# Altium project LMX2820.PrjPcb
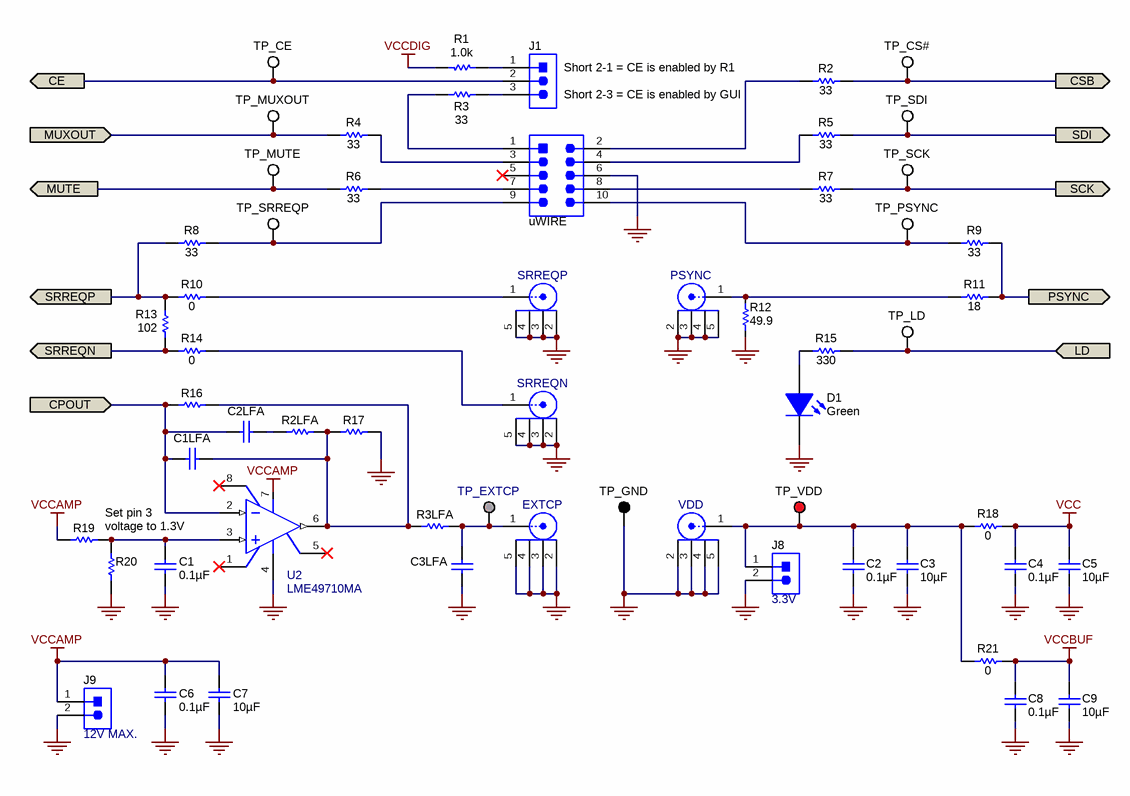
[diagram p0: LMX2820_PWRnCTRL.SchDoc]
TID: N/A; TechSupport: http://www.ti.com/support; SCH_Rev: A; PRJ_Title: LMX2820EVM; PRJ_Customer: Public Release; PCB_Rev: A; CopyrightYear: 2020
3 sheets, 127 parts. Net scope: flat (ports and power ports of the same name join across sheets).
Board file: LMX2820.PcbDoc
Sheets:
  LMX2820_PWRnCTRL.SchDoc
  LMX2820_SYNTH.SchDoc
  LMX2820_HW.SchDoc

## Sheet LMX2820_PWRnCTRL.SchDoc: Power supply and control interface
size Letter; Date: Not shown in title block; ApprovedBy: Not shown in title block; CheckedBy: Not shown in title block; Author: Not shown in title block; CompanyName: Not shown in title block; Engineer: Not shown in title block; Organization: Not shown in title block; Address1: Not shown in title block; Address2: Not shown in title block; Address3: Not shown in title block; Address4: Not shown in title block; DocumentNumber: 1; Revision: Use project parameter SCH_Rev; SheetNumber: 1; SheetTotal: 3; PageSetup: Record=PageOptions¦CenterHorizontal=True¦CenterVertical=True¦PrintScale=1.00¦XCorrection=1.00¦YCorrection=1.00¦PrintKind=0¦BorderSize=5000000¦LeftOffset=0¦BottomOffset=0¦Orientation=2¦PaperLength=1000¦PaperWidth=1000¦Scale=100¦PaperSource=15¦PrintQuality=600¦MediaType=1¦DitherType=10¦PaperKind=Letter¦PrintScaleMode=1

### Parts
C1  ValueDisplayed: 0.1µF  [0603]  (hidden comment: 885012206046)
C1LFA  885012206046  [0603]  (value not drawn)
C2  ValueDisplayed: 0.1µF  [0201_033]  (hidden comment: GRM033R61C104KE84D)
C2LFA  885012206046  [0603]  (value not drawn)
C3  ValueDisplayed: 10µF  [0603]  (hidden comment: GRM188R61A106KAALD)
C3LFA  885012206046  [0603]  (value not drawn)
C4  ValueDisplayed: 0.1µF  [0201_033]  (hidden comment: GRM033R61C104KE84D)
C5  ValueDisplayed: 10µF  [0603]  (hidden comment: GRM188R61A106KAALD)
C6  ValueDisplayed: 0.1µF  [0603]  (hidden comment: 885012206046)
C7  ValueDisplayed: 10µF  [0603]  (hidden comment: GRM188R61A106KAALD)
C8  ValueDisplayed: 0.1µF  [0201_033]  (hidden comment: GRM033R61C104KE84D)
C9  ValueDisplayed: 10µF  [0603]  (hidden comment: GRM188R61A106KAALD)
D1  value Green  [LED_LTST-C190]  (hidden comment: LTST-C190GKT)
J1  TSW-103-07-G-S  [TSW-103-07-G-S]  (value not drawn)
J2  uWIRE  [FCI_52601-S10-8LF]
J3  SRREQP  [FP-CON-SMA-EDGE-S_CONN_JACK-MFG]
J4  PSYNC  [FP-CON-SMA-EDGE-S_CONN_JACK-MFG]
J5  SRREQN  [FP-CON-SMA-EDGE-S_CONN_JACK-MFG]
J6  EXTCP  [FP-CON-SMA-EDGE-S_CONN_JACK-MFG]
J7  VDD  [FP-CON-SMA-EDGE-S_CONN_JACK-MFG]
J8  3.3V  [TSW-102-07-G-S]
J9  12V MAX.  [TSW-102-07-G-S]
R1  ValueDisplayed: 1.0k  [0603]  (hidden comment: CRCW06031K00JNEA)
R2  ValueDisplayed: 33  [0603]  (hidden comment: CRCW060333R0JNEA)
R2LFA  CRCW060333R0JNEA  [0603]  (value not drawn)
R3  ValueDisplayed: 33  [0603]  (hidden comment: CRCW060333R0JNEA)
R3LFA  CRCW06030000Z0EA  [0603]  (value not drawn)
R4  ValueDisplayed: 33  [0603]  (hidden comment: CRCW060333R0JNEA)
R5  ValueDisplayed: 33  [0603]  (hidden comment: CRCW060333R0JNEA)
R6  ValueDisplayed: 33  [0603]  (hidden comment: CRCW060333R0JNEA)
R7  ValueDisplayed: 33  [0603]  (hidden comment: CRCW060333R0JNEA)
R8  ValueDisplayed: 33  [0603]  (hidden comment: CRCW060333R0JNEA)
R9  ValueDisplayed: 33  [0603]  (hidden comment: CRCW060333R0JNEA)
R10  ValueDisplayed: 0  [0603]  (hidden comment: CRCW06030000Z0EA)
R11  ValueDisplayed: 18  [0603]  (hidden comment: CRCW060318R0JNEA)
R12  ValueDisplayed: 49.9  [0603]  (hidden comment: CRCW060349R9FKEA)
R13  ValueDisplayed: 102  [0603]  (hidden comment: CRCW0603102RFKEA)
R14  ValueDisplayed: 0  [0603]  (hidden comment: CRCW06030000Z0EA)
R15  ValueDisplayed: 330  [0603]  (hidden comment: CRCW0603330RJNEA)
R16  CRCW06030000Z0EA  [0603]  (value not drawn)
R17  CRCW06030000Z0EA  [0603]  (value not drawn)
R18  ValueDisplayed: 0  [0603]  (hidden comment: CRCW06030000Z0EA)
R19  CRCW06030000Z0EA  [0603]  (value not drawn)
R20  CRCW06030000Z0EA  [0603]  (value not drawn)
R21  ValueDisplayed: 0  [0603]  (hidden comment: CRCW06030000Z0EA)
TP1  TP_CE  [Keystone5002]
TP2  TP_CS#  [Keystone5002]
TP3  TP_MUXOUT  [Keystone5002]
TP4  TP_SDI  [Keystone5002]
TP5  TP_MUTE  [Keystone5002]
TP6  TP_SCK  [Keystone5002]
TP7  TP_SRREQP  [Keystone5002]
TP8  TP_PSYNC  [Keystone5002]
TP9  TP_LD  [Keystone5002]
TP10  TP_EXTCP  [TESTPOINT]  (no BOM)
TP11  TP_GND  [Keystone5001]
TP12  TP_VDD  [Keystone5000]
U2  LME49710MA  [D0008A_N]

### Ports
CE (out), CPOUT (in), CSB (out), LD (in), MUTE (out), MUXOUT (in), PSYNC (out), SCK (out), SDI (out), SRREQN (out), SRREQP (out)

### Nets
GND: C1.1 C2.2 C3.2 C3LFA.1 C4.2 C5.1 C6.2 C7.2 C8.2 C9.1 D1.2(K) J2.6 J3.2 J3.3 J3.4 J3.5 J4.2 J4.3 J4.4 J4.5 J5.2 J5.3 J5.4 J5.5 J6.2 J6.3 J6.4 J6.5 J7.2 J7.3 J7.4 J7.5 J8.2 J9.2 R12.1 R17.2 R20.1 TP11.1 U2.4(V-)
VCC: C4.1 C5.2 R18.1
VCCAMP: C6.1 C7.1 J9.1 R19.1 U2.7(V+)
VCCBUF: C8.1 C9.2 R21.2
VCCDIG: R1.2
CE: J1.2 TP1.1 ; port CE
CPOUT: C1LFA.1 C2LFA.1 R16.1 U2.2(-IN) ; port CPOUT
CSB: R2.2 TP2.1 ; port CSB
LD: R15.2 TP9.1 ; port LD
MUTE: R6.2 TP5.1 ; port MUTE
MUXOUT: R4.2 TP3.1 ; port MUXOUT
PSYNC: R9.2 R11.2 ; port PSYNC
SCK: R7.2 TP6.1 ; port SCK
SDI: R5.2 TP4.1 ; port SDI
SRREQN: R13.2 R14.1 ; port SRREQN
SRREQP: R8.2 R10.1 R13.1 ; port SRREQP
NetC1_2: C1.2 R19.2 R20.2 U2.3(+IN)
NetC1LFA_2: C1LFA.2 R2LFA.2 R3LFA.1 R16.2 R17.1 U2.6(OUTPUT)
NetC2_1: C2.1 C3.1 J7.1 J8.1 R18.2 R21.1 TP12.1
NetC2LFA_2: C2LFA.2 R2LFA.1
NetC3LFA_2: C3LFA.2 J6.1 R3LFA.2 TP10.1
NetD1_1: D1.1(A) R15.1
NetJ1_1: J1.1 R1.1
NetJ1_3: J1.3 R3.1
NetJ2_1: J2.1 R3.2
NetJ2_2: J2.2 R2.1
NetJ2_3: J2.3 R4.1
NetJ2_4: J2.4 R5.1
NetJ2_7: J2.7 R6.1
NetJ2_8: J2.8 R7.1
NetJ2_9: J2.9 R8.1 TP7.1
NetJ2_10: J2.10 R9.1 TP8.1
NetJ3_1: J3.1 R10.2
NetJ4_1: J4.1 R11.1 R12.2
NetJ5_1: J5.1 R14.2

Not connected (* = marked no-connect by the designer): J2 5*; U2 1(NC)* 5(NC)* 8(NC)*

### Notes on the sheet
- (near J1) Short 2-1 = CE is enabled by R1
- Short 2-3 = CE is enabled by GUI
- Set pin 3
- (near R19) voltage to 1.3V

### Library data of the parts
C1 C6 = CMP-0006829-4: CAP, CERM, 0.1 uF, 16 V, +/- 10%, X7R, 0603; Manufacturer: Wurth Elektronik; TaMin_C: -55°C; Polarized: N; SizeAreaWB_mm2: 4.68; Value1: Unknown; U/M: EA; Value: 0.1uF; TaMax_C: 125°C; SizeZ_mm: 1; SizeX_mm: 1.6; SizeY_mm: 0.8; Value2: 16V; SizeArea_mm2: 1.28; Cap_F: 100nF; AEC Category: Q200
C1LFA C2LFA C3LFA = CMP-0006829-4: CAP, CERM, 0.1 uF, 16 V, +/- 10%, X7R, 0603; Manufacturer: Wurth Elektronik; TaMin_C: -55°C; Polarized: N; SizeAreaWB_mm2: 4.68; Value1: Unknown; U/M: EA; Value: 0.1uF; TaMax_C: 125°C; SizeZ_mm: 1; SizeX_mm: 1.6; SizeY_mm: 0.8; Value2: 16V; SizeArea_mm2: 1.28; Cap_F: 100nF; AEC Category: Q200; ValueDisplayed: 0.1µF
C2 C4 C8 = CMP-0009717-2: CAP, CERM, 0.1 uF, 16 V, +/- 10%, X5R, 0201; Manufacturer: MuRata; TaMin_C: -55°C; Polarized: N; SizeAreaWB_mm2: 2.08; Value1: Unknown; U/M: EA; Value: 0.1uF; TaMax_C: 85°C; SizeZ_mm: 0.33; SizeX_mm: 0.6; SizeY_mm: 0.3; Cap_Case: 0201; Value2: 16V; SizeArea_mm2: 0.18; Cap_F: 100nF; AEC Category: Q200
C3 C5 C9 = CMP-0086193-1: CAP, CERM, 10 µF, 10 V,+/- 10%, X5R, 0603; Manufacturer: MuRata; SizeY_mm: 0.8; SizeAreaWB_mm2: 4.68; SizeX_mm: 1.6; SizeArea_mm2: 1.28; VDC_V: 10V; AEC Qualified: N; Value: 10uF; U/M: EA; SizeZ_mm: 1; TaMax_C: 85°C; AEC Category: Q200; TaMin_C: -55°C
C7 = CMP-0086193-1: CAP, CERM, 10 µF, 10 V,+/- 10%, X5R, 0603; Manufacturer: MuRata; SizeArea_mm2: 1.28; SizeY_mm: 0.8; TaMax_C: 85°C; TaMin_C: -55°C; VDC_V: 10V; Polarized: N; SizeAreaWB_mm2: 4.68; SizeZ_mm: 1; SizeX_mm: 1.6; AEC Category: Q200; U/M: EA; Value: 10uF
D1 = CMP-0002827-3: LED, Green, SMD; Manufacturer: Lite-On; Power_TotalModule: 100mW; Value2: 2.1V; Io_A: 20mA; Value1: 0.1W
J1 = CMP-0075407-2: Header, 100mil, 3x1, Gold, TH; Manufacturer: Samtec; Pitch_mm: 2.54; Cert_VDE: N; Gender: Male; Cert_CSA: Y; Voltage_V: 550V; Green_REACh: Passed; Current_A: 6.3A; Green_Lifecycle: Active; Row_Count: 1
J2 = CMP-0055434-2: Header (shrouded), 100mil, 5x2, Gold, SMT; Manufacturer: FCI; PartNumber: 52601-S10-8LF; Green_Lifecycle: Active; Green_REACh: Passed
J3-J7 = CMP-0088000-4: CONN SMA JACK STR EDGE MNT; Manufacturer: RF Solutions Ltd.; PartNumber: CON-SMA-EDGE-S; ContactFinish: Gold; Shrouded: true
J8 = CMP-0075405-3: Header, 100mil, 2x1, Gold, TH; Manufacturer: Samtec; Current_A: 6.3A; Green_Lifecycle: Active; Pitch_mm: 2.54; Cert_CSA: Y; Cert_VDE: N; Green_REACh: Passed; Row_Count: 1; Gender: Male; Voltage_V: 550V
J9 = CMP-0075405-3: Header, 100mil, 2x1, Gold, TH; Manufacturer: Samtec; Pitch_mm: 2.54; Cert_VDE: N; Gender: Male; Cert_CSA: Y; Voltage_V: 550V; Green_REACh: Passed; Current_A: 6.3A; Green_Lifecycle: Active; Row_Count: 1
R1 = CMP-0025729-4: RES, 1.0 k, 5%, 0.1 W, AEC-Q200 Grade 0, 0603; Manufacturer: Vishay-Dale; SizeY_mm: 0.8; AEC Grade: 0; TempCo: 200 ppm/C; SizeX_mm: 1.6; SizeArea_mm2: 1.28; VDC_V: 75V; AEC Qualified: Y; Value: 1.0k; SizeZ_mm: 1; AEC Category: Q200; Value2: 0.1W; Power_W: 100mW; Value_Code: 1k00; EIA_Code: E24; Res_ohm: 1k
R2 R2LFA R4-R7 R9 = CMP-0025787-4: RES, 33, 5%, 0.1 W, AEC-Q200 Grade 0, 0603; Manufacturer: Vishay-Dale; Power_W: 100mW; TempCo: 200 ppm/C; Value_Code: 33R0; Value: 33; EIA_Code: E24; SizeX_mm: 1.6; SizeY_mm: 0.8; SizeZ_mm: 1; Value2: 0.1W; SizeArea_mm2: 1.28; AEC Qualified: Y; VDC_V: 75V; AEC Category: Q200; AEC Grade: 0
R3 = CMP-0025787-4: RES, 33, 5%, 0.1 W, AEC-Q200 Grade 0, 0603; Manufacturer: Vishay-Dale; TempCo: 200 ppm/C; Value: 33; SizeZ_mm: 1; SizeX_mm: 1.6; SizeY_mm: 0.8; Value2: 0.1W; SizeArea_mm2: 1.28; AEC Qualified: Y; VDC_V: 75V; AEC Grade: 0; AEC Category: Q200; Power_W: 100mW; Value_Code: 33R0; EIA_Code: E24
R3LFA R16 R17 R19 R20 = CMP-0025697-4: RES, 0, 5%, 0.1 W, AEC-Q200 Grade 0, 0603; Manufacturer: Vishay-Dale; Power_W: 100mW; TempCo: 200 ppm/C; Value_Code: 0000; Value: 0; EIA_Code: E24; SizeX_mm: 1.6; SizeY_mm: 0.8; SizeZ_mm: 1; Value2: 0.1W; SizeArea_mm2: 1.28; AEC Qualified: Y; VDC_V: 75V; AEC Category: Q200
R8 = CMP-0025787-4: RES, 33, 5%, 0.1 W, AEC-Q200 Grade 0, 0603; Manufacturer: Vishay-Dale; Power_W: 100mW; TempCo: 200 ppm/C; Value_Code: 33R0; Value: 33; EIA_Code: E24; SizeX_mm: 1.6; SizeY_mm: 0.8; SizeZ_mm: 1; Value2: 0.1W; SizeArea_mm2: 1.28; AEC Qualified: Y; AEC Grade: 0; AEC Category: Q200; VDC_V: 75V
R10 R14 R21 = CMP-0025697-4: RES, 0, 5%, 0.1 W, AEC-Q200 Grade 0, 0603; Manufacturer: Vishay-Dale; Power_W: 100mW; TempCo: 200 ppm/C; Value_Code: 0000; Value: 0; EIA_Code: E24; SizeX_mm: 1.6; SizeY_mm: 0.8; SizeZ_mm: 1; Value2: 0.1W; SizeArea_mm2: 1.28; AEC Qualified: Y; AEC Category: Q200; VDC_V: 75V
R11 = CMP-0025728-4: RES, 18, 5%, 0.1 W, AEC-Q200 Grade 0, 0603; Manufacturer: Vishay-Dale; Power_W: 100mW; TempCo: 200 ppm/C; Value_Code: 18R0; Value: 18; EIA_Code: E24; SizeX_mm: 1.6; SizeY_mm: 0.8; SizeZ_mm: 1; Value2: 0.1W; SizeArea_mm2: 1.28; AEC Qualified: Y; VDC_V: 75V; AEC Category: Q200; AEC Grade: 0
R12 = CMP-0022448-4: RES, 49.9, 1%, 0.1 W, AEC-Q200 Grade 0, 0603; Manufacturer: Vishay-Dale; Power_W: 100mW; TempCo: 100 ppm/C; Value_Code: 49R9; Value: 49.9; EIA_Code: E96; SizeX_mm: 1.6; SizeY_mm: 0.8; SizeZ_mm: 1; Value2: 0.1W; SizeArea_mm2: 1.28; AEC Qualified: Y; VDC_V: 75V; AEC Category: Q200; AEC Grade: 0
R13 = CMP-0021993-5: RES, 102, 1%, 0.1 W, AEC-Q200 Grade 0, 0603; Manufacturer: Vishay-Dale; Power_W: 100mW; TempCo: 100 ppm/C; Value_Code: 102R; Value: 102; EIA_Code: E96; SizeX_mm: 1.6; SizeY_mm: 0.8; SizeZ_mm: 1; Value2: 0.1W; SizeArea_mm2: 1.28; AEC Qualified: Y; VDC_V: 75V; AEC Category: Q200; AEC Grade: 0
R15 = CMP-0025785-4: RES, 330, 5%, 0.1 W, AEC-Q200 Grade 0, 0603; Manufacturer: Vishay-Dale; Power_W: 100mW; TempCo: 200 ppm/C; Value_Code: 330R; Value: 330; EIA_Code: E24; SizeX_mm: 1.6; SizeY_mm: 0.8; SizeZ_mm: 1; Value2: 0.1W; SizeArea_mm2: 1.28; AEC Qualified: Y; VDC_V: 75V; AEC Category: Q200; AEC Grade: 0
R18 = CMP-0025697-4: RES, 0, 5%, 0.1 W, AEC-Q200 Grade 0, 0603; Manufacturer: Vishay-Dale; Value: 0; SizeZ_mm: 1; SizeX_mm: 1.6; SizeY_mm: 0.8; Value2: 0.1W; SizeArea_mm2: 1.28; Power_W: 100mW; TempCo: 200 ppm/C; Value_Code: 0000; EIA_Code: E24; AEC Qualified: Y; VDC_V: 75V; AEC Category: Q200
TP1 TP3 TP7 TP9 = CMP-0055139-1: Test Point, Miniature, White, TH; Manufacturer: Keystone; CNHeader: FALSE; Green_Lifecycle: Active; Green_REACh: Passed; ContactFinish: Silver; CT: TRUE
TP2 TP4-TP6 TP8 = CMP-0055139-1: Test Point, Miniature, White, TH; Manufacturer: Keystone; ContactFinish: Silver; Green_Lifecycle: Active; Green_REACh: Passed; CNHeader: FALSE; CT: TRUE
TP10 = CMP-0078143-3: TEST POINT.  No entry in BOM.
TP11 = CMP-0055138-1: Test Point, Miniature, Black, TH; Manufacturer: Keystone; ContactFinish: Silver; Green_Lifecycle: Active; Green_REACh: Passed; CNHeader: FALSE; CT: TRUE
TP12 = CMP-0055137-1: Test Point, Miniature, Red, TH; Manufacturer: Keystone; ContactFinish: Silver; Green_Lifecycle: Active; Green_REACh: Passed; CNHeader: FALSE; CT: TRUE
U2 = CMP-0068996-2: High Performance, High Fidelity Audio Operational Amplifier, 8-pin Narrow SOIC, Pb-Free; Manufacturer: Texas Instruments; PartNumber: LME49710MA/NOPB; CompType: IC; AEC Category: Q200; AEC Qualified: N; SizeAreaWB_mm2: 56.58; SizeArea_mm2: 30.38; SizeX_mm: 4.9; SizeY_mm: 6.2; SizeZ_mm: 1.75

## Sheet LMX2820_SYNTH.SchDoc: Synthesizer
size Letter; Date: Not shown in title block; ApprovedBy: Not shown in title block; CheckedBy: Not shown in title block; Author: Not shown in title block; CompanyName: Not shown in title block; Engineer: Not shown in title block; Organization: Not shown in title block; Address1: Not shown in title block; Address2: Not shown in title block; Address3: Not shown in title block; Address4: Not shown in title block; DocumentNumber: 2; Revision: Use project parameter SCH_Rev; SheetNumber: 2; SheetTotal: 3; PageSetup: Record=PageOptions¦CenterHorizontal=True¦CenterVertical=True¦PrintScale=1.00¦XCorrection=1.00¦YCorrection=1.00¦PrintKind=0¦BorderSize=5000000¦LeftOffset=0¦BottomOffset=0¦Orientation=2¦PaperLength=1000¦PaperWidth=1000¦Scale=100¦PaperSource=15¦PrintQuality=600¦MediaType=1¦DitherType=10¦PaperKind=Letter¦PrintScaleMode=1
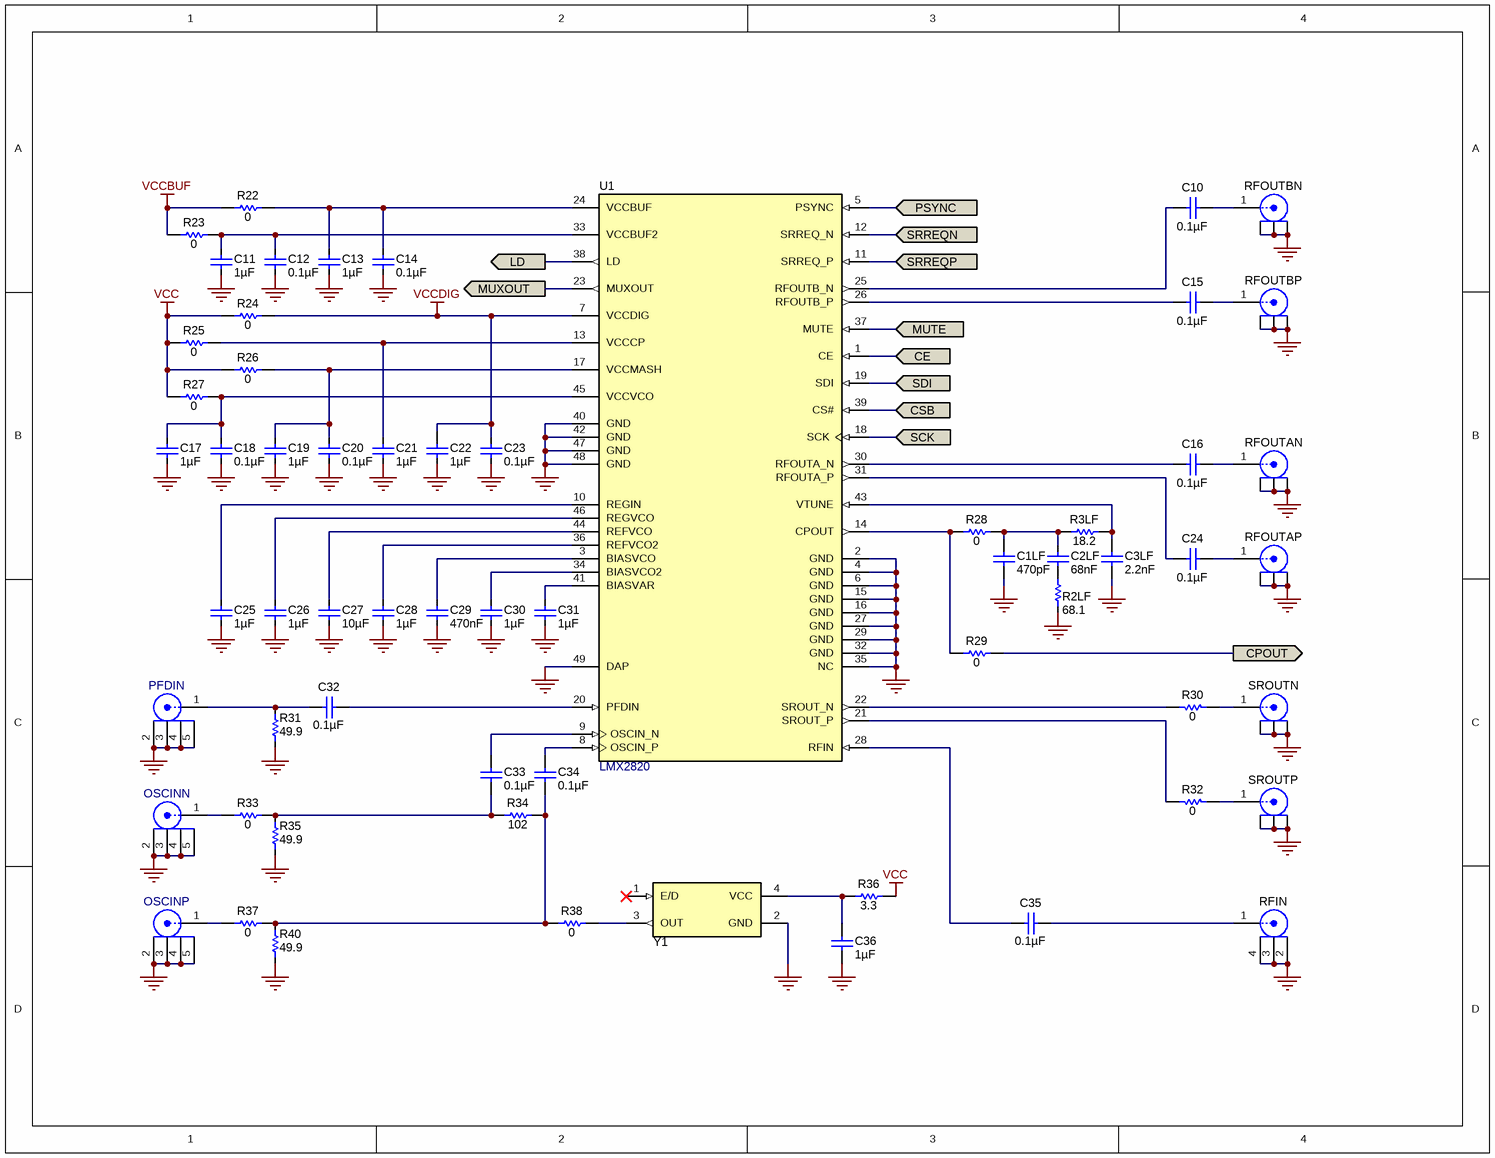
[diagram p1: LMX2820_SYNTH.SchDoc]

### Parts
C1LF  ValueDisplayed: 470pF  [0603]  (hidden comment: 885012006012)
C2LF  Cap_F: 68nF  [0603]  (hidden comment: 885012206070)
C3LF  Cap_F: 2.2nF  [0603]  (hidden comment: 885012206036)
C10  ValueDisplayed: 0.1µF  [0201_033L]  (hidden comment: ATC530Z104KT10T)
C11  ValueDisplayed: 1µF  [0402]  (hidden comment: GRM155R61E105KA12D)
C12  ValueDisplayed: 0.1µF  [0201_033]  (hidden comment: GRM033R61C104KE84D)
C13  ValueDisplayed: 1µF  [0402]  (hidden comment: GRM155R61E105KA12D)
C14  ValueDisplayed: 0.1µF  [0201_033]  (hidden comment: GRM033R61C104KE84D)
C15  ValueDisplayed: 0.1µF  [0201_033L]  (hidden comment: ATC530Z104KT10T)
C16  ValueDisplayed: 0.1µF  [0201_033L]  (hidden comment: ATC530Z104KT10T)
C17  ValueDisplayed: 1µF  [0402]  (hidden comment: GRM155R61E105KA12D)
C18  ValueDisplayed: 0.1µF  [0201_033]  (hidden comment: GRM033R61C104KE84D)
C19  ValueDisplayed: 1µF  [0402]  (hidden comment: GRM155R61E105KA12D)
C20  ValueDisplayed: 0.1µF  [0201_033]  (hidden comment: GRM033R61C104KE84D)
C21  ValueDisplayed: 1µF  [0402]  (hidden comment: GRM155R61E105KA12D)
C22  ValueDisplayed: 1µF  [0402]  (hidden comment: GRM155R61E105KA12D)
C23  ValueDisplayed: 0.1µF  [0201_033]  (hidden comment: GRM033R61C104KE84D)
C24  ValueDisplayed: 0.1µF  [0201_033L]  (hidden comment: ATC530Z104KT10T)
C25  ValueDisplayed: 1µF  [0402]  (hidden comment: GRM155R61E105KA12D)
C26  ValueDisplayed: 1µF  [0402]  (hidden comment: GRM155R61E105KA12D)
C27  ValueDisplayed: 10µF  [0603]  (hidden comment: GRM188R61A106KAALD)
C28  ValueDisplayed: 1µF  [0402]  (hidden comment: GRM155R61E105KA12D)
C29  Cap_F: 470nF  [0603]  (hidden comment: CGA3E3X7R1E474K080AB)
C30  ValueDisplayed: 1µF  [0402]  (hidden comment: GRM155R61E105KA12D)
C31  ValueDisplayed: 1µF  [0402]  (hidden comment: GRM155R61E105KA12D)
C32  ValueDisplayed: 0.1µF  [0201_033]  (hidden comment: GRM033R61C104KE84D)
C33  ValueDisplayed: 0.1µF  [0201_033]  (hidden comment: GRM033R61C104KE84D)
C34  ValueDisplayed: 0.1µF  [0201_033]  (hidden comment: GRM033R61C104KE84D)
C35  ValueDisplayed: 0.1µF  [0201_033L]  (hidden comment: ATC530Z104KT10T)
C36  Cap_F: 1µF  [0603]  (hidden comment: 885012206052)
J10  RFOUTBN  [Johnson_142-0771-831]
J11  RFOUTBP  [Johnson_142-0771-831]
J12  RFOUTAN  [Johnson_142-0771-831]
J13  RFOUTAP  [Johnson_142-0771-831]
J14  PFDIN  [FP-CON-SMA-EDGE-S_CONN_JACK-MFG]
J15  SROUTN  [Johnson_142-0771-831]
J16  SROUTP  [Johnson_142-0771-831]
J17  OSCINN  [FP-CON-SMA-EDGE-S_CONN_JACK-MFG]
J18  OSCINP  [FP-CON-SMA-EDGE-S_CONN_JACK-MFG]
J19  RFIN  [Johnson_142-0771-831]
R2LF  ValueDisplayed: 68.1  [0603]  (hidden comment: CRCW060368R1FKEA)
R3LF  ValueDisplayed: 18.2  [0603]  (hidden comment: CRCW060318R2FKEA)
R22  ValueDisplayed: 0  [0603]  (hidden comment: CRCW06030000Z0EA)
R23  ValueDisplayed: 0  [0603]  (hidden comment: CRCW06030000Z0EA)
R24  ValueDisplayed: 0  [0603]  (hidden comment: CRCW06030000Z0EA)
R25  ValueDisplayed: 0  [0603]  (hidden comment: CRCW06030000Z0EA)
R26  ValueDisplayed: 0  [0603]  (hidden comment: CRCW06030000Z0EA)
R27  ValueDisplayed: 0  [0603]  (hidden comment: CRCW06030000Z0EA)
R28  ValueDisplayed: 0  [0603]  (hidden comment: CRCW06030000Z0EA)
R29  ValueDisplayed: 0  [0603]  (hidden comment: CRCW06030000Z0EA)
R30  ValueDisplayed: 0  [0201]  (hidden comment: CRCW02010000Z0ED)
R31  ValueDisplayed: 49.9  [0603]  (hidden comment: CRCW060349R9FKEA)
R32  ValueDisplayed: 0  [0201]  (hidden comment: CRCW02010000Z0ED)
R33  ValueDisplayed: 0  [0603]  (hidden comment: CRCW06030000Z0EA)
R34  ValueDisplayed: 102  [0603]  (hidden comment: CRCW0603102RFKEA)
R35  ValueDisplayed: 49.9  [0603]  (hidden comment: CRCW060349R9FKEA)
R36  ValueDisplayed: 3.3  [0603]  (hidden comment: CRCW06033R30JNEA)
R37  ValueDisplayed: 0  [0603]  (hidden comment: CRCW06030000Z0EA)
R38  ValueDisplayed: 0  [0603]  (hidden comment: CRCW06030000Z0EA)
R40  ValueDisplayed: 49.9  [0603]  (hidden comment: CRCW060349R9FKEA)
U1  LMX2820  [RTC0048A]
Y1  CWX813-100.0M  [OSC_CWX]  (value not drawn)

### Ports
CE (in), CPOUT (out), CSB (in), LD (out), MUTE (in), MUXOUT (out), PSYNC (in), SCK (in), SDI (in), SRREQN (in), SRREQP (in)

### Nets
GND: C1LF.2 C3LF.2 C11.2 C12.2 C13.1 C14.1 C17.2 C18.2 C19.2 C20.1 C21.2 C22.2 C23.1 C25.2 C26.2 C27.1 C28.1 C29.2 C30.1 C31.2 C36.2 J10.2 J10.3 J10.4 J11.2 J11.3 J11.4 J12.2 J12.3 J12.4 J13.2 J13.3 J13.4 J14.2 J14.3 J14.4 J14.5 J15.2 J15.3 J15.4 J16.2 J16.3 J16.4 J17.2 J17.3 J17.4 J17.5 J18.2 J18.3 J18.4 J18.5 J19.2 J19.3 J19.4 R2LF.1 R31.1 R35.1 R40.2 U1.2(GND) U1.4(GND) U1.6(GND) U1.15(GND) U1.16(GND) U1.27(GND) U1.29(GND) U1.32(GND) U1.35(NC) U1.40(GND) U1.42(GND) U1.47(GND) U1.48(GND) U1.49(DAP) Y1.2(GND)
VCC: R24.2 R25.2 R26.2 R27.2 R36.2
VCCBUF: R22.2 R23.2
VCCDIG: C22.1 C23.2 R24.1 U1.7(VCCDIG)
CE: U1.1(CE) ; port CE
CPOUT: R29.1 ; port CPOUT
CSB: U1.39(CS#) ; port CSB
LD: U1.38(LD) ; port LD
MUTE: U1.37(MUTE) ; port MUTE
MUXOUT: U1.23(MUXOUT) ; port MUXOUT
PSYNC: U1.5(PSYNC) ; port PSYNC
SCK: U1.18(SCK) ; port SCK
SDI: U1.19(SDI) ; port SDI
SRREQN: U1.12(SRREQ_N) ; port SRREQN
SRREQP: U1.11(SRREQ_P) ; port SRREQP
NetC1LF_1: C1LF.1 C2LF.1 R3LF.2 R28.1
NetC2LF_2: C2LF.2 R2LF.2
NetC3LF_1: C3LF.1 R3LF.1 U1.43(VTUNE)
NetC10_1: C10.1 J10.1
NetC10_2: C10.2 U1.25(RFOUTB_N)
NetC11_1: C11.1 C12.1 R23.1 U1.33(VCCBUF2)
NetC13_2: C13.2 C14.2 R22.1 U1.24(VCCBUF)
NetC15_1: C15.1 J11.1
NetC15_2: C15.2 U1.26(RFOUTB_P)
NetC16_1: C16.1 J12.1
NetC16_2: C16.2 U1.30(RFOUTA_N)
NetC17_1: C17.1 C18.1 R27.1 U1.45(VCCVCO)
NetC19_1: C19.1 C20.2 R26.1 U1.17(VCCMASH)
NetC21_1: C21.1 R25.1 U1.13(VCCCP)
NetC24_1: C24.1 J13.1
NetC24_2: C24.2 U1.31(RFOUTA_P)
NetC25_1: C25.1 U1.10(REGIN)
NetC26_1: C26.1 U1.46(REGVCO)
NetC27_2: C27.2 U1.44(REFVCO)
NetC28_2: C28.2 U1.36(REFVCO2)
NetC29_1: C29.1 U1.3(BIASVCO)
NetC30_2: C30.2 U1.34(BIASVCO2)
NetC31_1: C31.1 U1.41(BIASVAR)
NetC32_1: C32.1 U1.20(PFDIN)
NetC32_2: C32.2 J14.1 R31.2
NetC33_1: C33.1 U1.9(OSCIN_N)
NetC33_2: C33.2 R33.2 R34.1 R35.2
NetC34_1: C34.1 U1.8(OSCIN_P)
NetC34_2: C34.2 R34.2 R37.2 R38.2 R40.1
NetC35_1: C35.1 U1.28(RFIN)
NetC35_2: C35.2 J19.1
NetC36_1: C36.1 R36.1 Y1.4(VCC)
NetJ15_1: J15.1 R30.2
NetJ16_1: J16.1 R32.2
NetJ17_1: J17.1 R33.1
NetJ18_1: J18.1 R37.1
NetR28_2: R28.2 R29.2 U1.14(CPOUT)
NetR30_1: R30.1 U1.22(SROUT_N)
NetR32_1: R32.1 U1.21(SROUT_P)
NetR38_1: R38.1 Y1.3(OUT)

Not connected (* = marked no-connect by the designer): Y1 1(E/D)*

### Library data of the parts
C1LF = CMP-0080734-1: CAP, CERM, 470 pF, 10 V,+/- 5%, C0G/NP0, 0603; Manufacturer: Wurth Elektronik; TaMin_C: -55°C; Polarized: N; SizeAreaWB_mm2: 4.68; U/M: EA; Value: 470pF; TaMax_C: 125°C; SizeZ_mm: 1; SizeX_mm: 1.6; SizeY_mm: 0.8; Value2: 10V; SizeArea_mm2: 1.28; AEC Category: Q200
C2LF = CMP-0750069-1: CAP, CERM, 0.068 µF, 25 V,+/- 10%, X7R, 0603; Manufacturer: Wurth Elektronik; TaMin_C: -55°C; Polarized: N; SizeAreaWB_mm2: 4.68; U/M: EA; Value: 0.068uF; TaMax_C: 125°C; SizeZ_mm: 1; SizeX_mm: 1.6; SizeY_mm: 0.8; Value2: 25V; SizeArea_mm2: 1.28; AEC Category: Q200
C3LF = CMP-0006827-4: CAP, CERM, 2200 pF, 16 V, +/- 10%, X7R, 0603; Manufacturer: Wurth Elektronik; AEC Qualified: N; TaMin_C: -55°C; AEC Category: Q200; SizeZ_mm: 1; SizeY_mm: 0.8; ValueDisplayed: 2200pF; SizeArea_mm2: 1.28; Value2: 16V; U/M: EA; SizeX_mm: 1.6; SizeAreaWB_mm2: 4.68; Value1: Unknown; TaMax_C: 125°C; Value: 2200pF
C10 C15 C16 C24 C35 = CMP-0076713-1: CAP, CERM, 0.1 µF, 10 V,+/- 10%, X5R, 0201; Manufacturer: American Technical Ceramics; TaMin_C: -55°C; Polarized: N; SizeAreaWB_mm2: 2.08; U/M: EA; Value: 0.1uF; TaMax_C: 85°C; SizeZ_mm: 0.33; SizeX_mm: 0.6; SizeY_mm: 0.3; Cap_Case: 0201; Value2: 10V; SizeArea_mm2: 0.18; AEC Qualified: No; Cap_F: 100nF; AEC Category: Q200
C11 C13 C17 C19 C21 C22 C25 C26 C30 = CMP-0006608-2: CAP, CERM, 1 uF, 25 V, +/- 10%, X5R, 0402; Manufacturer: MuRata; TaMin_C: -55°C; Polarized: N; SizeAreaWB_mm2: 3; Value1: Unknown; U/M: EA; Value: 1uF; TaMax_C: 85°C; SizeZ_mm: 0.6; SizeX_mm: 1; SizeY_mm: 0.5; Value2: 25V; AEC Category: Q200
C12 C14 C18 C20 C23 = CMP-0009717-2: CAP, CERM, 0.1 uF, 16 V, +/- 10%, X5R, 0201; Manufacturer: MuRata; U/M: EA; TaMax_C: 85°C; Value2: 16V; SizeZ_mm: 0.33; AEC Qualified: N; TaMin_C: -55°C; SizeY_mm: 0.3; AEC Category: Q200; Cap_Case: 0201; Value1: Unknown; SizeAreaWB_mm2: 2.08; Cap_F: 100nF; SizeX_mm: 0.6; Value: 0.1uF; SizeArea_mm2: 0.18
C27 = CMP-0086193-1: as C3 on sheet LMX2820_PWRnCTRL
C28 C31 = CMP-0006608-2: CAP, CERM, 1 uF, 25 V, +/- 10%, X5R, 0402; Manufacturer: MuRata; SizeY_mm: 0.5; SizeAreaWB_mm2: 3; SizeX_mm: 1; VDC_V: 25V; Value1: Unknown; Value: 1uF; U/M: EA; SizeZ_mm: 0.6; TaMax_C: 85°C; AEC Category: Q200; Polarized: N; TaMin_C: -55°C
C29 = CMP-0007092-5: CAP, CERM, 0.47 uF, 25 V, +/- 10%, X7R, AEC-Q200 Grade 1, 0603; Manufacturer: TDK; TaMin_C: -55°C; Polarized: N; SizeAreaWB_mm2: 4.68; Value1: Unknown; U/M: EA; Value: 0.47uF; TaMax_C: 125°C; SizeZ_mm: 1; SizeX_mm: 1.6; SizeY_mm: 0.8; Value2: 25V; SizeArea_mm2: 1.28; AEC Qualified: Y; AEC Category: Q200
C32-C34 = CMP-0009717-2: as C2 on sheet LMX2820_PWRnCTRL
C36 = CMP-0006831-4: CAP, CERM, 1 uF, 16 V, +/- 10%, X7R, 0603; Manufacturer: Wurth Elektronik; TaMin_C: -55°C; Polarized: N; SizeAreaWB_mm2: 4.68; Value1: Unknown; U/M: EA; Value: 1uF; TaMax_C: 125°C; SizeZ_mm: 1; SizeX_mm: 1.6; SizeY_mm: 0.8; Value2: 16V; SizeArea_mm2: 1.28; AEC Category: Q200
J10-J13 J15 J16 J19 = CMP-0055844-3: JACK, SMA, 50 Ohm, Gold, Edge Mount; PartNumber: 142-0771-831; Manufacturer: Cinch Connectivity; Voltage_V: 170V; Gender: Female
J14 J17 J18 = CMP-0088000-4: as J3 on sheet LMX2820_PWRnCTRL
R2LF = CMP-0022553-4: RES, 68.1, 1%, 0.1 W, AEC-Q200 Grade 0, 0603; Manufacturer: Vishay-Dale; Power_W: 100mW; TempCo: 100 ppm/C; Value_Code: 68R1; Value: 68.1; EIA_Code: E96; SizeX_mm: 1.6; SizeY_mm: 0.8; SizeZ_mm: 1; Value2: 0.1W; SizeArea_mm2: 1.28; AEC Qualified: Y; VDC_V: 75V; AEC Category: Q200; AEC Grade: 0
R3LF = CMP-0022099-4: RES, 18.2, 1%, 0.1 W, AEC-Q200 Grade 0, 0603; Manufacturer: Vishay-Dale; Power_W: 100mW; TempCo: 100 ppm/C; Value_Code: 18R2; Value: 18.2; EIA_Code: E96; SizeX_mm: 1.6; SizeY_mm: 0.8; SizeZ_mm: 1; Value2: 0.1W; SizeArea_mm2: 1.28; AEC Qualified: Y; VDC_V: 75V; AEC Category: Q200; AEC Grade: 0
R22-R27 = CMP-0025697-4: as R10 on sheet LMX2820_PWRnCTRL
R28 R29 R33 R37 R38 = CMP-0025697-4: as R3LFA on sheet LMX2820_PWRnCTRL
R30 R32 = CMP-0027008-4: RES, 0, 5%, 0.05 W, 0201; Manufacturer: Vishay-Dale; TempCo: ppm/C; Value: 0; SizeZ_mm: 0.26; SizeX_mm: 0.6; SizeY_mm: 0.3; Value2: 0.05W; SizeArea_mm2: 0.18; AEC Qualified: N; AEC Category: Q200; Power_W: 50mW; Value_Code: 0000; EIA_Code: E24
R31 R35 R40 = CMP-0022448-4: RES, 49.9, 1%, 0.1 W, AEC-Q200 Grade 0, 0603; Manufacturer: Vishay-Dale; Power_W: 100mW; TempCo: 100 ppm/C; Value_Code: 49R9; Value: 49.9; EIA_Code: E96; SizeX_mm: 1.6; SizeY_mm: 0.8; SizeZ_mm: 1; Value2: 0.1W; SizeArea_mm2: 1.28; AEC Qualified: Y; VDC_V: 75V; AEC Grade: 0; AEC Category: Q200
R34 = CMP-0021993-5: as R13 on sheet LMX2820_PWRnCTRL
R36 = CMP-0025805-4: RES, 3.3, 5%, 0.1 W, AEC-Q200 Grade 0, 0603; Manufacturer: Vishay-Dale; Power_W: 100mW; TempCo: 200 ppm/C; Value_Code: 3R30; Value: 3.3; EIA_Code: E24; SizeX_mm: 1.6; SizeY_mm: 0.8; SizeZ_mm: 1; Value2: 0.1W; SizeArea_mm2: 1.28; AEC Qualified: Y; VDC_V: 75V; AEC Category: Q200; AEC Grade: 0
U1 = CMP-0750054-4: 22-GHz Wideband PLLatinum™ RF Synthesizer With Phase Synchronization and JESD204B Support, RTC0048A (PVQFN-64); Manufacturer: Texas Instruments; PartNumber: LMX2820RTCR; AEC Qualified: N; SizeZ_mm: 0.9; SizeAreaWB_mm2: 81; AEC Category: Q200; CompType: IC; SizeArea_mm2: 49; SizeX_mm: 7
Y1 = CMP-0004571-3: OSC 100.0000 MHz 3.3V +-25PPM SMD; Manufacturer: Connor-Winfield; TaMax_C: 70°C; TaMin_C: -20°C; CompType: Crystal; Frequency Stability: +/-25ppm; Frequency_Fixed: 100MHz

## Sheet LMX2820_HW.SchDoc: Hardware
size Letter; Date: Not shown in title block; ApprovedBy: Not shown in title block; CheckedBy: Not shown in title block; Author: Not shown in title block; CompanyName: Not shown in title block; Engineer: Not shown in title block; Organization: Not shown in title block; Address1: Not shown in title block; Address2: Not shown in title block; Address3: Not shown in title block; Address4: Not shown in title block; DocumentNumber: 3; Revision: Use project parameter SCH_Rev; SheetNumber: 3; SheetTotal: 3; PageSetup: Record=PageOptions¦CenterHorizontal=True¦CenterVertical=True¦PrintScale=1.00¦XCorrection=1.00¦YCorrection=1.00¦PrintKind=0¦BorderSize=5000000¦LeftOffset=0¦BottomOffset=0¦Orientation=2¦PaperLength=1000¦PaperWidth=1000¦Scale=100¦PaperSource=15¦PrintQuality=600¦MediaType=1¦DitherType=10¦PaperKind=Letter¦PrintScaleMode=1
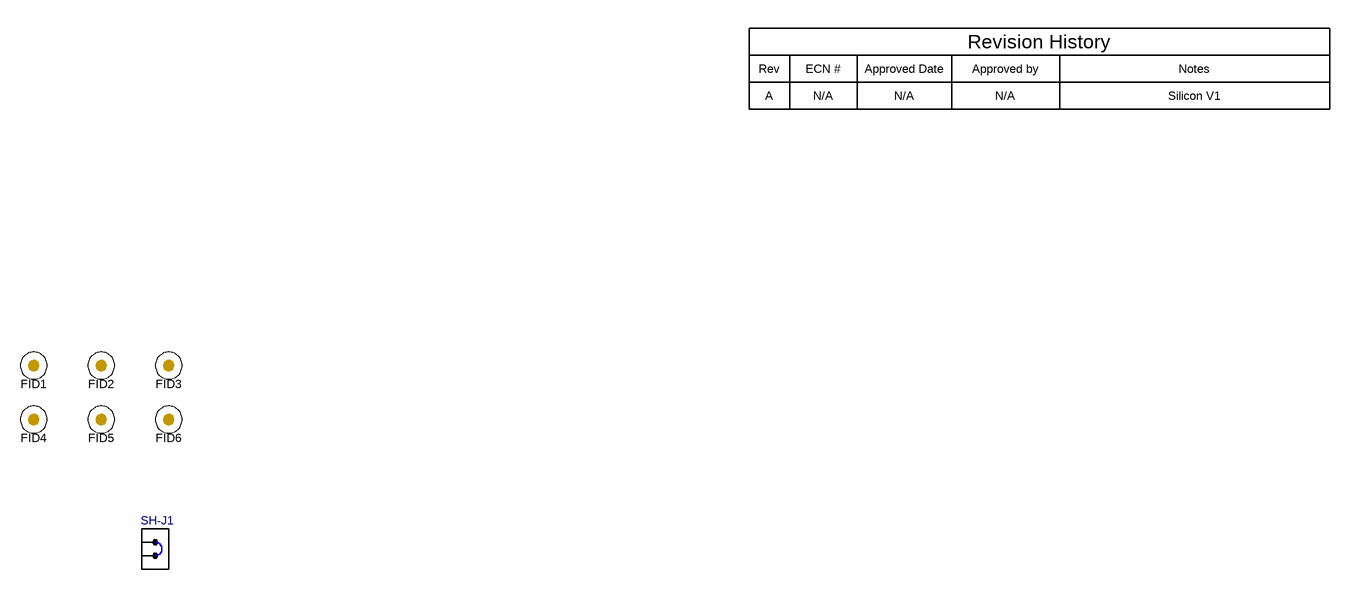
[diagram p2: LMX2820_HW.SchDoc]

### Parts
FID1  Fiducial  [Fiducial10-20]  (value not drawn)
FID2  Fiducial  [Fiducial10-20]  (value not drawn)
FID3  Fiducial  [Fiducial10-20]  (value not drawn)
FID4  Fiducial  [Fiducial10-20]  (value not drawn)
FID5  Fiducial  [Fiducial10-20]  (value not drawn)
FID6  Fiducial  [Fiducial10-20]  (value not drawn)
SH-J1  SNT-100-BK-G  [SNT-100-BK-G]  (value not drawn)

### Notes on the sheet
- Rev
- A
- ECN #
- N/A
- Approved Date
- Approved by
- Revision History
- Notes
- Silicon V1

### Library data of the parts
FID1-FID6 = CMP-0077181-1: Fiducial mark.  There is nothing to buy or mount.
SH-J1 = CMP-0003623-3: Shunt, 100mil, Gold plated, Black; Alternate PartNumber: 969102-0000-DA; Manufacturer: Samtec; Alternate Manufacturer: 3M; Value: 1x2; Note: You can "mate" this to a header by matching the designator.  i.e. use SH-J3 for header J3

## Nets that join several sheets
GND: LMX2820_PWRnCTRL (39 pins), LMX2820_SYNTH (73 pins)
VCC: LMX2820_PWRnCTRL (C4.1 C5.2 R18.1), LMX2820_SYNTH (5 pins)
VCCBUF: LMX2820_PWRnCTRL (C8.1 C9.2 R21.2), LMX2820_SYNTH (R22.2 R23.2)
VCCDIG: LMX2820_PWRnCTRL (R1.2), LMX2820_SYNTH (C22.1 C23.2 R24.1 U1.7)
CE: LMX2820_PWRnCTRL (J1.2 TP1.1), LMX2820_SYNTH (U1.1)
CPOUT: LMX2820_PWRnCTRL (C1LFA.1 C2LFA.1 R16.1 U2.2), LMX2820_SYNTH (R29.1)
CSB: LMX2820_PWRnCTRL (R2.2 TP2.1), LMX2820_SYNTH (U1.39)
LD: LMX2820_PWRnCTRL (R15.2 TP9.1), LMX2820_SYNTH (U1.38)
MUTE: LMX2820_PWRnCTRL (R6.2 TP5.1), LMX2820_SYNTH (U1.37)
MUXOUT: LMX2820_PWRnCTRL (R4.2 TP3.1), LMX2820_SYNTH (U1.23)
PSYNC: LMX2820_PWRnCTRL (R9.2 R11.2), LMX2820_SYNTH (U1.5)
SCK: LMX2820_PWRnCTRL (R7.2 TP6.1), LMX2820_SYNTH (U1.18)
SDI: LMX2820_PWRnCTRL (R5.2 TP4.1), LMX2820_SYNTH (U1.19)
SRREQN: LMX2820_PWRnCTRL (R13.2 R14.1), LMX2820_SYNTH (U1.12)
SRREQP: LMX2820_PWRnCTRL (R8.2 R10.1 R13.1), LMX2820_SYNTH (U1.11)

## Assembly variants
001: not fitted C1 C1LFA C2LFA C3LFA C6 C7 C36 FID1 FID2 FID3 FID4 FID5 FID6 J3 J4 J5 J6 J7 J9 J17 R2LFA R3 R3LFA R10 R11 R12 R13 R14 R16 R17 R19 R20 R29 R33 R34 R36 R38 R41 R42 U2 Y1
